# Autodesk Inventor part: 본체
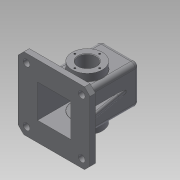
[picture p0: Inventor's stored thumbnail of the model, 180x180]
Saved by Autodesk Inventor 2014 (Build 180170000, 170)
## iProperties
Created: 2016-02
Part Number: 본체
Material: Generic
Document SubType Name: Modeling
Designer: user
Density: 1 g/cm^3
Appearance: Default
Author: user
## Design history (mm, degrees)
sketch "Sketch1"
  geometry: L1 (-35, -60)-(35, -60); L2 (35, -60)-(35, 60); L3 (35, 60)-(-35, 60); L4 (-35, 60)-(-35, -60); L5 (-35, -60)-(35, 60); L6 (35, -60)-(-35, 60); 1 further point
  constraints: 12 end point, 2 midpoint
extrude "Extrusion1" new body sketch "Sketch1" stored distance "d6" = 70; taper "d7" = 0 deg
sketch "Sketch3"
  geometry: L1 (70, -70)-(70, 0) reference; L2 (0, 0)-(70, 0) reference; L3 (0, 0)-(0, -70) reference; L4 (70, -70)-(0, -70) reference; L5 (-30, -100)-(100, -100); L6 (100, -100)-(100, 30); L7 (100, 30)-(-30, 30); L8 (-30, 30)-(-30, -100); L9 (-30, -100)-(100, 30); L10 (100, -100)-(-30, 30); 1 further point
  constraints: 12 end point, 2 midpoint
extrude "Extrusion2" join sketch "Sketch3" distance "d9" = 10; taper "d10" = 0 deg
sketch "Sketch4"
  geometry: C1 r 27.5 at (0, 0); 1 further point
  constraints: 1 centre point, 1 coincident
extrude "Extrusion3" join sketch "Sketch4" distance "d11" = 13; taper "d12" = 0 deg
mirror "Mirror1"
sketch "Sketch5"
  geometry: L1 (-65, -60)-(-65, -50) reference; L2 (-65, -50)-(-35, -50) reference; L3 (-35, -50)-(-35, 60) reference; L4 (-35, 60)-(35, 60) reference; L5 (35, 60)-(35, -50) reference; L6 (35, -50)-(65, -50) reference; L7 (65, -50)-(65, -60) reference; L8 (65, -60)-(-65, -60) reference; L9 (20, 60)-(18.237, 70); L10 (18.237, 70)-(0, 70); L11 (0, 70)-(0, 60); L12 (0, 60)-(20, 60); 1 further point
  constraints: 8 end point, 1 horizontal, 1 midpoint, 1 point on line, 1 vertical
  dimensions: "d13" = 20 distance of L11.end L9.start; "d14" = 100 deg angle of L4 L9; "d15" = 10 distance of L10.end L11.end
revolve "Revolution1" sketch "Sketch5" stored, may be unused: angle "d16" = 90 deg
sketch "Sketch6"
  geometry: L1 (-65, -60)-(-65, -50) reference; L2 (-65, -50)-(-35, -50) reference; L3 (-35, -50)-(-35, 60) reference; L4 (-35, 60)-(-20, 60) reference; L5 (-20, 60)-(-18.237, 70) reference; L6 (-18.237, 70)-(18.237, 70) reference; L7 (18.237, 70)-(20, 60) reference; L8 (20, 60)-(35, 60) reference; L9 (35, 60)-(35, -50) reference; L10 (35, -50)-(65, -50) reference; L11 (65, -50)-(65, -60) reference; L12 (65, -60)-(-65, -60) reference; L13 (-50, -50)-(-35, 35.069); 1 further point
  constraints: 2 end point, 1 midpoint, 1 point on line
  dimensions: "d17" = 100 deg angle of L2 L13; "d18" = 15 distance from line of L1 L13.start
feature "Rib1" sketch "Sketch6" dims "d19" = 1, "d20" = 10, "d21" = 0, "d22" = 0, "d23" = 1, "d24" = 1
mirror "Mirror2"
sketch "Sketch8"
  geometry: L1 (27.5, 48)-(27.5, 35) reference; L2 (27.5, 35)-(60, 35) reference; L3 (60, 35)-(60, 20) reference; L4 (60, 20)-(70, 18.237) reference; L5 (70, 18.237)-(70, -18.237) reference; L6 (70, -18.237)-(60, -20) reference; L7 (60, -20)-(60, -35) reference; L8 (60, -35)-(27.5, -35) reference; L9 (27.5, -35)-(27.5, -48) reference; L10 (27.5, -48)-(-27.5, -48) reference; L11 (-27.5, -48)-(-27.5, -35) reference; L12 (-27.5, -35)-(-50, -35) reference; L13 (-50, -35)-(-50, -65) reference; L14 (-50, -65)-(-60, -65) reference; L15 (-60, -65)-(-60, 65) reference; L16 (-60, 65)-(-50, 65) reference; L17 (-50, 65)-(-50, 35) reference; L18 (-50, 35)-(-27.5, 35) reference; L19 (-27.5, 35)-(-27.5, 48) reference; L20 (-27.5, 48)-(27.5, 48) reference; L21 (-60, 30)-(55, 30); L22 (55, 30)-(55, -30); L23 (55, -30)-(-60, -30); L24 (-60, 30)-(-60, -30); 1 further point
  constraints: 8 end point, 2 point on line
  dimensions: "d25" = 5 distance between parallel lines of L18 L21; "d26" = 5 distance between parallel lines of L23 L12; "d27" = 5 distance between parallel lines of L7 L22
extrude "Extrusion4" cut sketch "Sketch8" stored distance "d28" = 60; taper "d29" = 0 deg
sketch "Sketch9"
  geometry: L1 (27.5, 48)-(27.5, 35) reference; L2 (27.5, 35)-(60, 35) reference; L3 (60, 35)-(60, 20) reference; L4 (60, 20)-(70, 18.237) reference; L5 (70, 18.237)-(70, -18.237) reference; L6 (70, -18.237)-(60, -20) reference; L7 (60, -20)-(60, -35) reference; L8 (60, -35)-(27.5, -35) reference; L9 (27.5, -35)-(27.5, -48) reference; L10 (27.5, -48)-(-27.5, -48) reference; L11 (-27.5, -48)-(-27.5, -35) reference; L12 (-27.5, -35)-(-50, -35) reference; L13 (-50, -35)-(-50, -65) reference; L14 (-50, -65)-(-60, -65) reference; L15 (-60, -65)-(-60, -30) reference; L16 (-60, -30)-(55, -30) reference; L17 (55, -30)-(55, 30) reference; L18 (55, 30)-(-60, 30) reference; L19 (-60, 30)-(-60, 65) reference; L20 (-60, 65)-(-50, 65) reference; L21 (-50, 65)-(-50, 35) reference; L22 (-50, 35)-(-27.5, 35) reference; L23 (-27.5, 35)-(-27.5, 48) reference; L24 (-27.5, 48)-(27.5, 48) reference; L25 (27.5, 30)-(0, 30); L26 (0, 30)-(0, 23); L27 (27.5, 30)-(20.5, 23); L28 (0, 23)-(20.5, 23); 1 further point
  constraints: 8 end point, 2 point on line
revolve "Revolution2" sketch "Sketch9" stored, may be unused: angle "d33" = 90 deg
mirror "Mirror3"
fillet "Fillet1" dims "d34" = 8
fillet "Fillet2" dims "d35" = 3
chamfer "Chamfer1" distance "d36" = 10; stored, may be unused: second distance "d37" = 2, angle "d38" = 45 deg
sketch "Sketch10"
  geometry: L1 (90, 100)-(-20, 100) reference; L2 (-30, 90)-(-30, -20) reference; C1 r 6 at (-15, 85); 1 further point
  constraints: 1 centre point
  dimensions: "d39" = 12 diameter of C1; "d40" = 15 distance from line of C1.centre L1; "d41" = 15 distance from line of C1.centre L2
extrude "Extrusion5" cut sketch "Sketch10" stored distance "d42" = 60; taper "d43" = 0 deg
mirror "Mirror4"
pattern_linear "Rectangular Pattern1"
fillet "Fillet3" dims "d47" = 8
fillet "Fillet4" dims "d48" = 0.5
sketch "Sketch11"
  geometry: L1 (-20.762, 45.72)-(20.762, 45.72); L2 (20.762, 45.72)-(20.762, 34.28); L3 (20.762, 34.28)-(-20.762, 34.28); L4 (-20.762, 34.28)-(-20.762, 45.72); L5 (-20.762, 45.72)-(20.762, 34.28); L6 (20.762, 45.72)-(-20.762, 34.28); L7 (-18.237, 70)-(18.237, 70) reference; L8 (35, -50)-(35, 52) reference; 1 further point
  constraints: 4 end point, 1 midpoint, 2 other
  dimensions: "d49" = 30 distance from line of point (0, 40) L7; "d50" = 35 distance from line of L8 point (0, 40)
emboss "Emboss1" sketch "Sketch11" dims "d51" = 0.5, "d52" = 0
fillet "Fillet5" dims "d53" = 3
fillet "Fillet6" dims "d54" = 3
fillet "Fillet7" dims "d55" = 3
hole "Hole1" diameter "d58" = 28; stored, may be unused: countersink angle "d62" = 90 deg, drill point angle "d64" = 0 deg; dims "d56" = 10, "d57" = 10, "d59" = 6, "d60" = 4, "d61" = 2, "d63" = 4
hole "Hole2" diameter "d67" = 21; stored, may be unused: countersink angle "d71" = 90 deg, drill point angle "d73" = 0 deg; dims "d65" = 10, "d66" = 10, "d68" = 6, "d69" = 4, "d70" = 2, "d72" = 4
hole "Hole3" diameter "d76" = 32; stored, may be unused: countersink angle "d80" = 90 deg, drill point angle "d82" = 0 deg; dims "d74" = 10, "d75" = 10, "d77" = 6, "d78" = 4, "d79" = 2, "d81" = 4
sketch "Sketch12"
  geometry: C1 r 27.5 at (0, 0) reference; 2 further points
  constraints: 1 coincident, 1 vertical alignment, 2 other
hole "Hole4" sketch "Sketch12" at (0, 22.5) diameter "d83" = 3.242; stored, may be unused: countersink angle "d87" = 90 deg, drill point angle "d89" = 118 deg; dims "d84" = 8, "d85" = 4, "d86" = 2, "d88" = 10
pattern_circular "Circular Pattern1" dims angle "d91" = 360 deg
mirror "Mirror5"
fillet "Fillet8" dims "d93" = 0.5
chamfer "Chamfer2" distance "d94" = 1; stored, may be unused: second distance "d95" = 2, angle "d96" = 45 deg
body "Solid1"
node "Project Cut Edges1"
node "Project Cut Edges2"
node "Project Cut Edges4"
node "Project Cut Edges5"
